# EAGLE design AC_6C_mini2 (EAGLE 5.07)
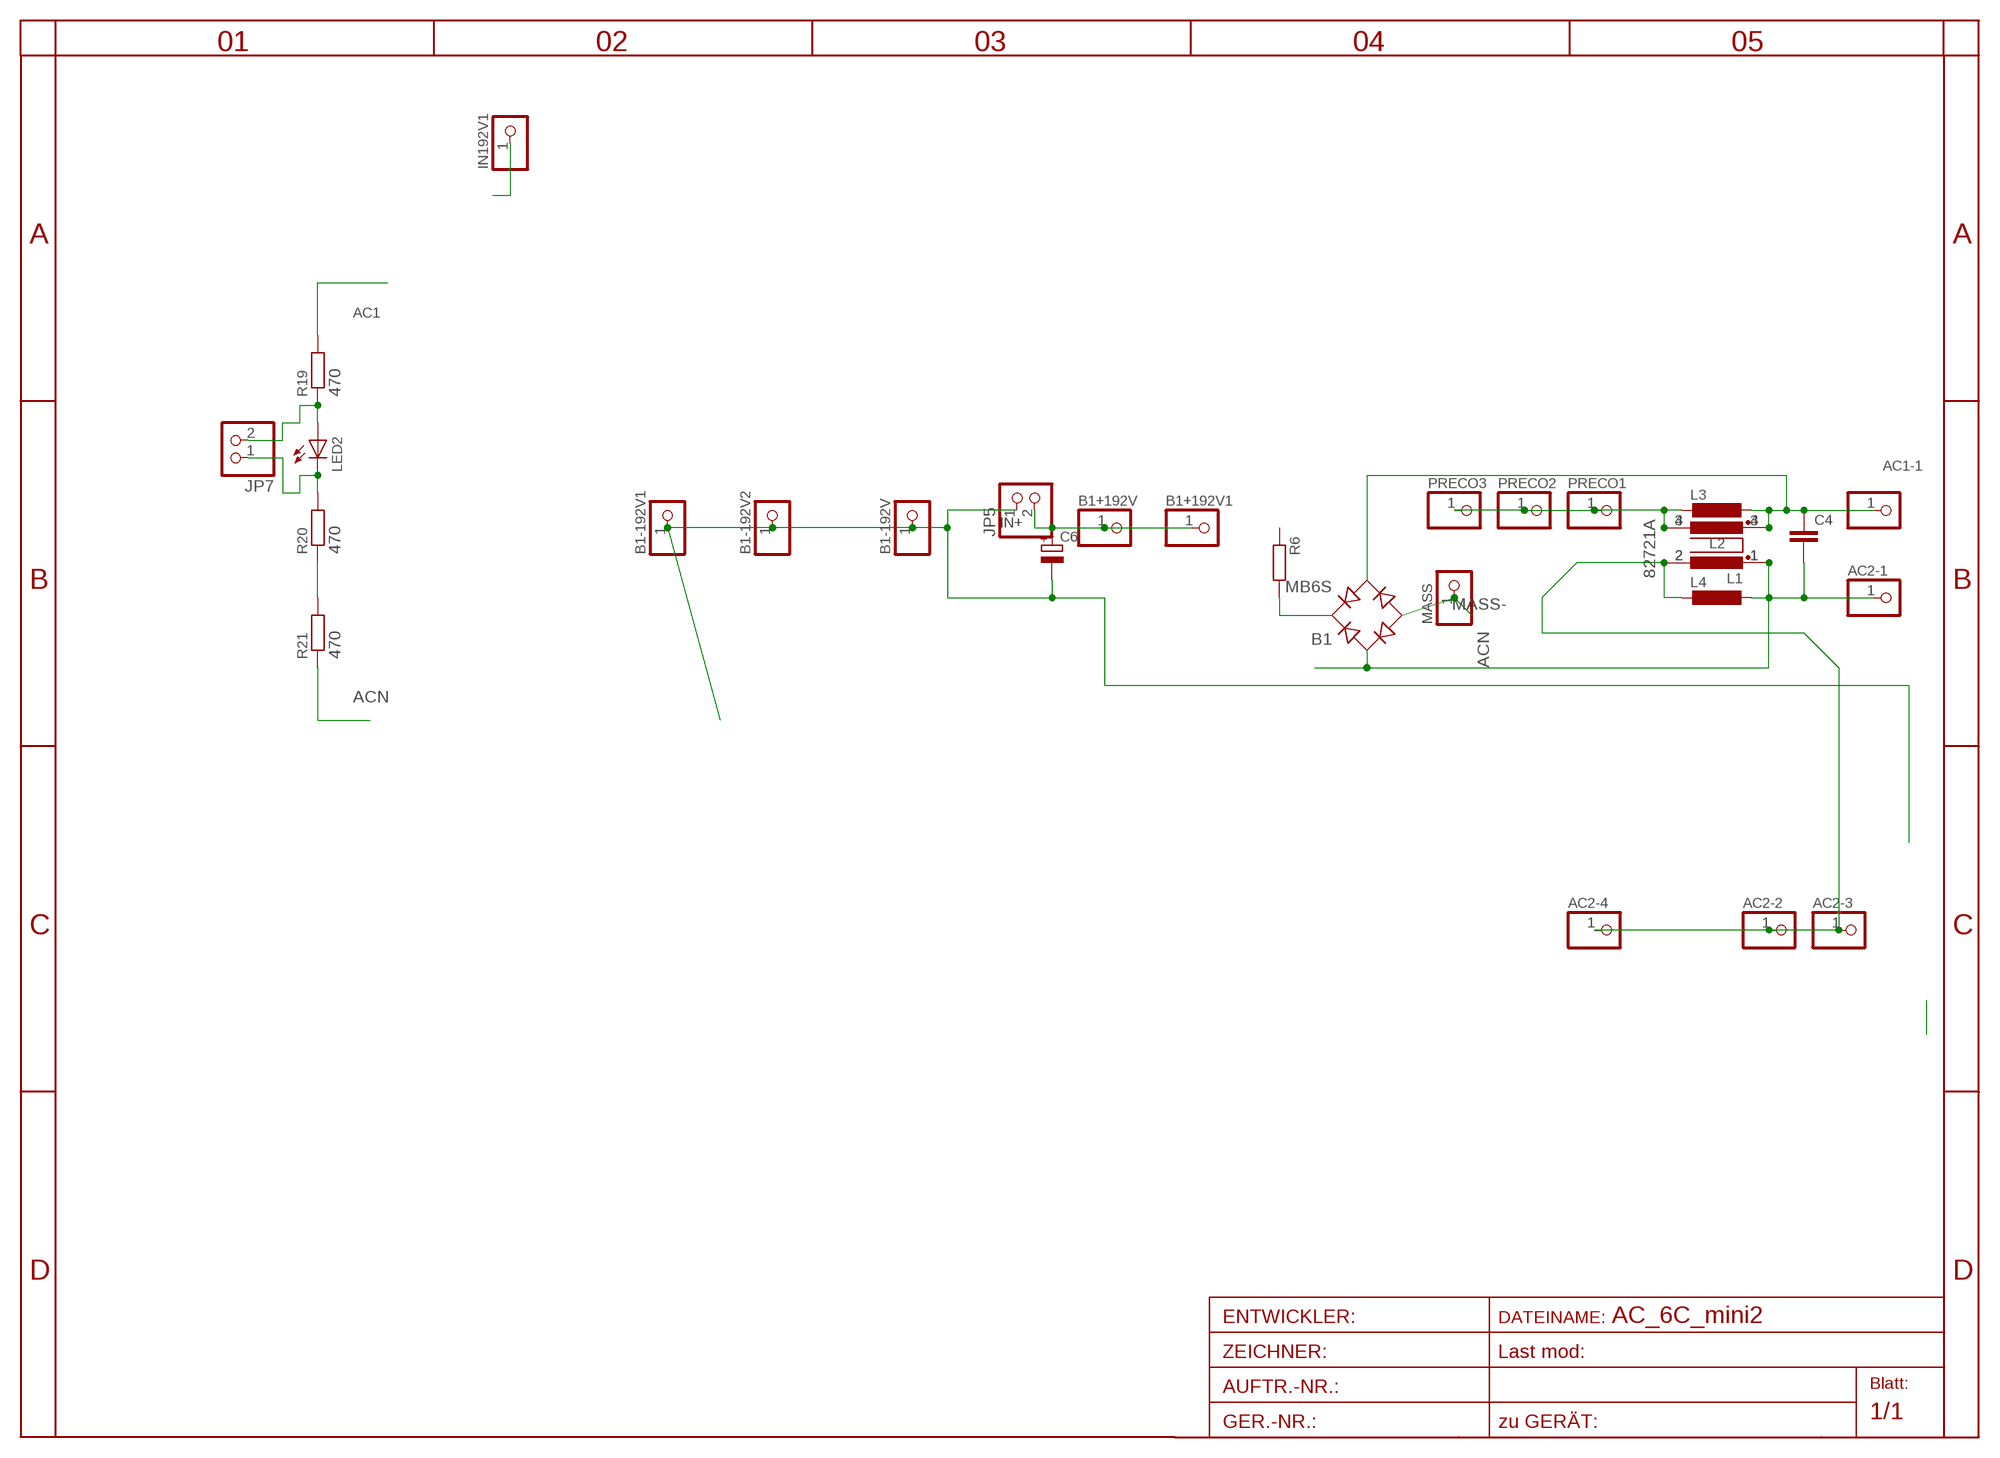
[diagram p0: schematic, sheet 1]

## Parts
AC1-1  PINHD-1X14.5MM  [1X4MM5]
AC2-1  PINHD-1X14.5MM  [1X4MM5]
AC2-2  PINHD-1X13MM2  [1X3MM2]
AC2-3  PINHD-1X13MM2  [1X3MM2]
AC2-4  PINHD-1X12MM3  [1X2MM3]
B1  MB6S  [SOIC-4]
B1+192V  PINHD-1X13MM2  [1X3MM2]
B1+192V1  PINHD-1X13MM2  [1X3MM2]
B1-192V  PINHD-1X13MM2  [1X3MM2]
B1-192V1  PINHD-1X13MM2  [1X3MM2]
B1-192V2  PINHD-1X13MM2  [1X3MM2]
C4  C-EU102-043X133  [C102-043X133]
C6  CPOL-EUE10-20  [EB20D]
IN192V1  PINHD-1X13MM2  [1X3MM2]
JP5  PINHD-1X2STR  [1X02]
JP7  PINHD-1X2STR  [1X02]
L1  R1405VB1  [B1]
L2  82721A  [82721A]
L3  L-EU2200-15.24  [2200-15.24]
L4  L-EU2200-15.24  [2200-15.24]
LED2  LED3MM  [LED3MM]
MASS  PINHD-1X13MM2  [1X3MM2]
PRECO1  PINHD-1X12MM3  [1X2MM3]
PRECO2  PINHD-1X13MM2  [1X3MM2]
PRECO3  PINHD-1X13MM2  [1X3MM2]
R6  R-EU_0207/60  [0207/60]
R19  470  R-EU_0204/5  [0204/5]
R20  470  R-EU_0204/2V  [0204V]
R21  470  R-EU_0204/5  [0204/5]

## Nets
AC1: AC1-1.1 B1.~2(AC2) C4.1 L1.3 L2.4 L3.1 R19.2
ACN: AC2-1.1 B1.~1(AC1) C4.2 L1.1 L2.1 L4.1 R21.1
IN+: B1+192V1.1 B1+192V.1 C6.+ IN192V1.1 JP5.2
INN: AC2-2.1 AC2-3.1 AC2-4.1 L1.2 L2.2 L4.2
MASS-: B1-192V1.1 B1-192V2.1 B1-192V.1 B1.- C6.- JP5.1 MASS.1
N$6: JP7.2 LED2.A R19.1
N$9: JP7.1 LED2.K(C) R20.2
N$13: R20.1 R21.2
N$33: B1.+ R6.2
PRECOIL: L1.4 L2.3 L3.2 PRECO1.1 PRECO2.1 PRECO3.1
Unconnected: R6.1

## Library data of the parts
AC1-1 AC2-1-AC2-4 B1+192V B1+192V1 B1-192V B1-192V1 B1-192V2 IN192V1 MASS PRECO1-PRECO3 = pinhead:PINHD-1X1: PIN HEADER
B1 = rectifier:MB*S: Bridge Rectifier Source: http://www.fairchildsemi.com/ds/MB/MB6S.pdf
C4 = rcl:C-EU: CAPACITOR, European symbol
C6 = rcl:CPOL-EU: POLARIZED CAPACITOR, European symbol
JP5 JP7 = pinhead:PINHD-1X2: PIN HEADER
L1 = inductor-nkl:R1405V: Übertrager (verlustarm) bis typ. 400kHz Power transformer (low loss) up to typ. 400kHz
L2 = inductors:82721A: FILTER
L3 L4 = rcl:L-EU: INDUCTOR, European symbol
LED2 = led:LED: LED
R6 R19-R21 = rcl-2:R-EU_: RESISTOR, European symbol

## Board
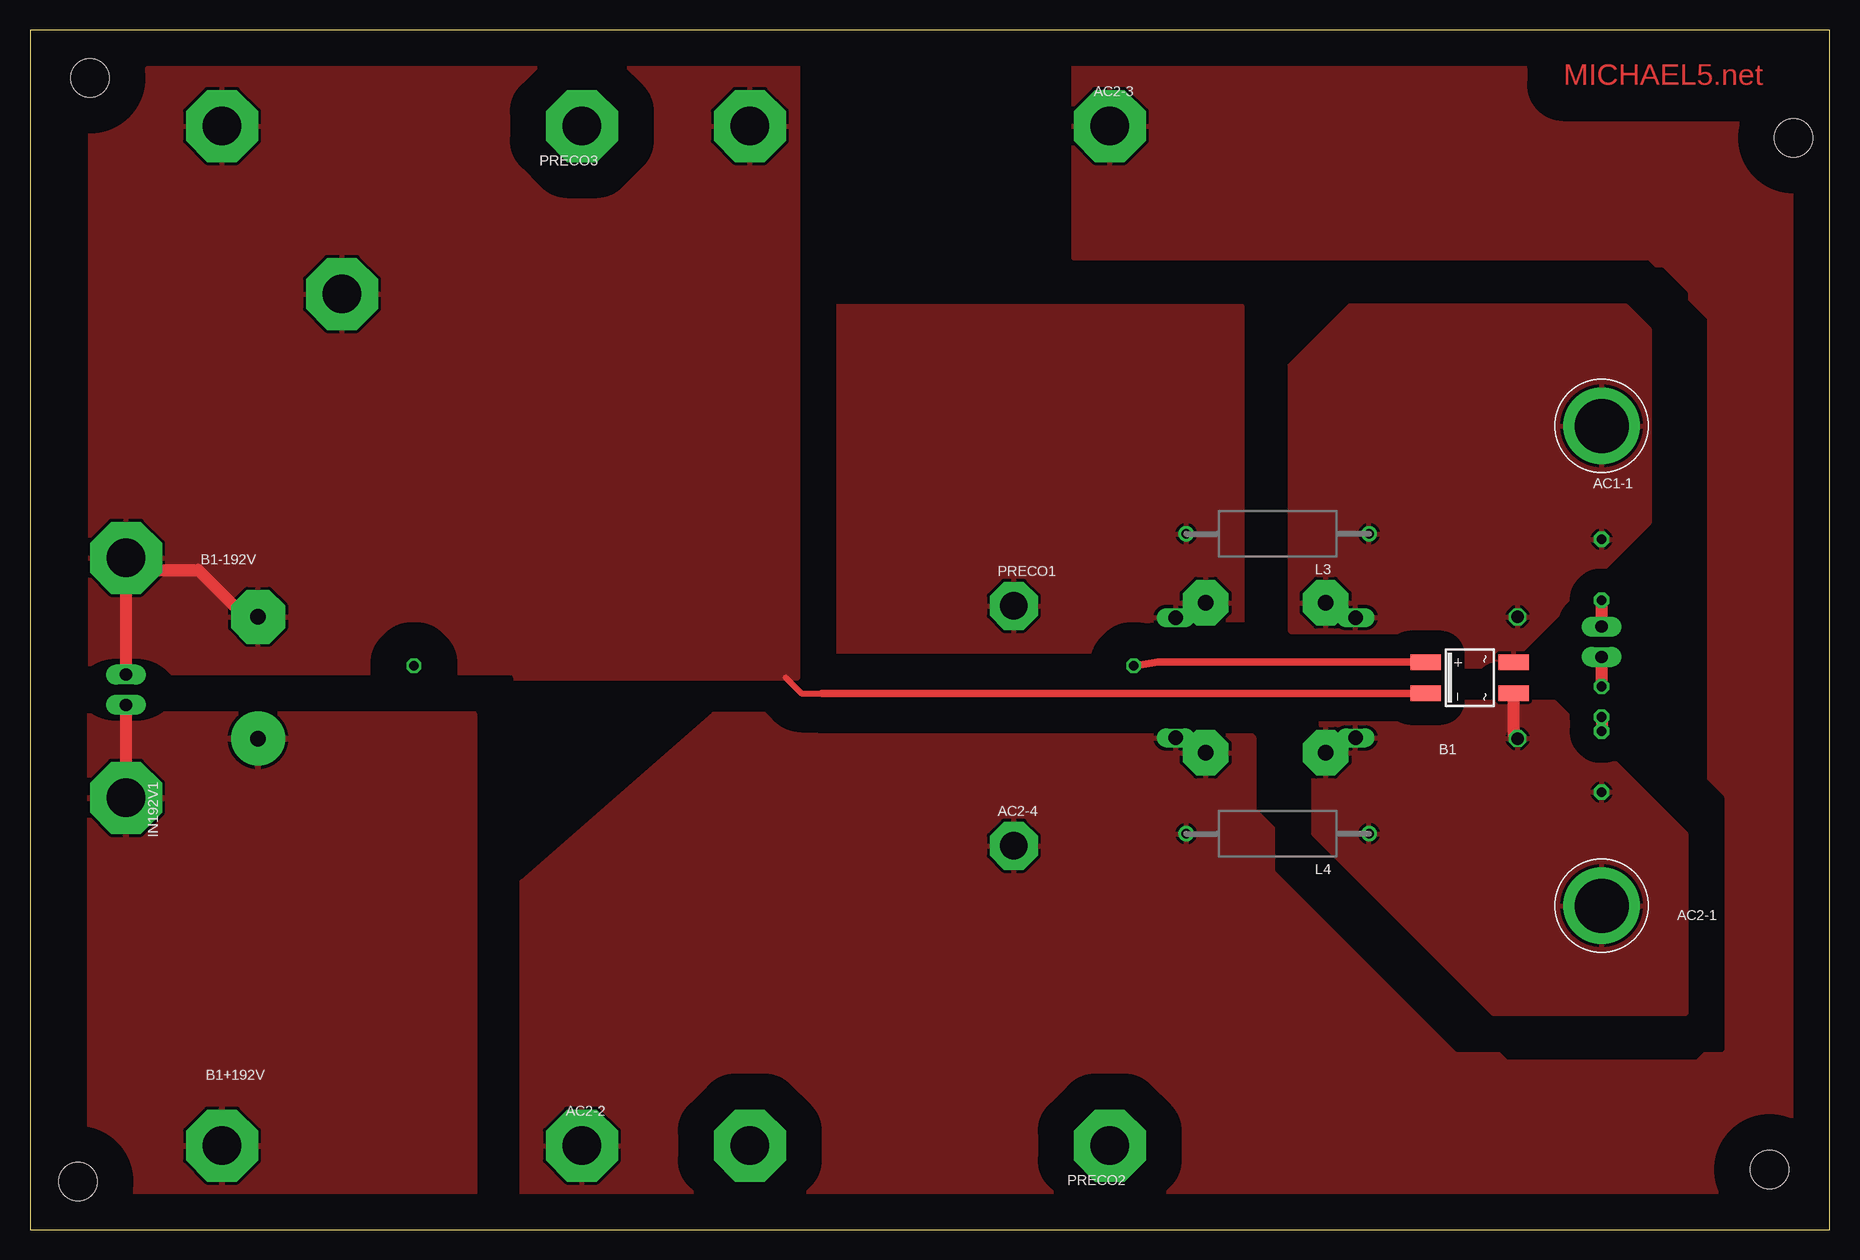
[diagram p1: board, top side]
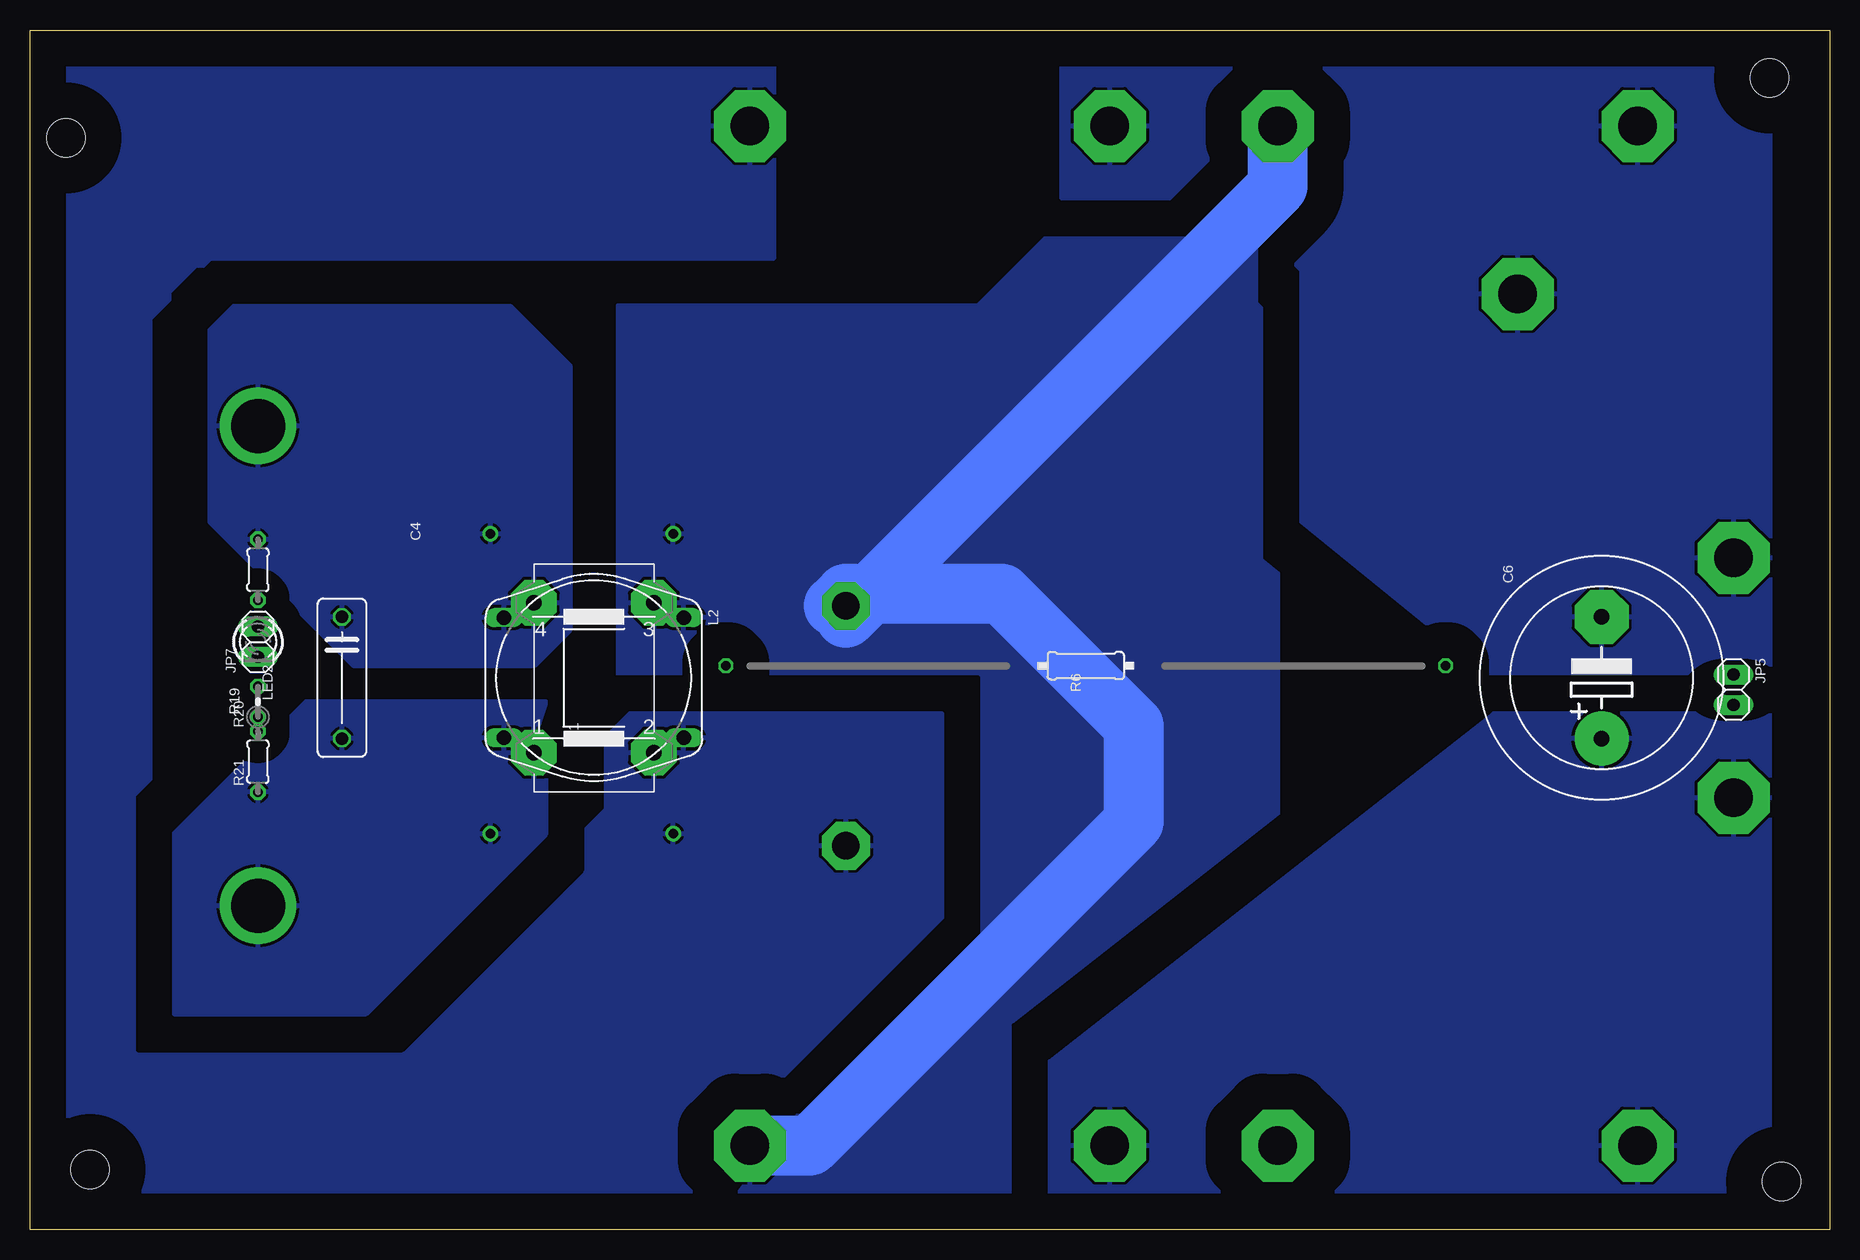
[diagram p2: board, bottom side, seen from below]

Size 150 x 100 mm. Coordinates in mm from the lower left corner, seen from the top.
Outline: 0,0 150,0 150,100 0,100 0,0
Copper layers (1*16): Top 0.035mm / dielectric 1.5mm / Bottom 0.035mm
Design rules "default *": minimum track width 12mil, minimum drill 24mil, track to track 8mil, track to pad 8mil, pad to pad 8mil, via to via 8mil, smd to smd 8mil, copper to edge 40mil, drill to drill 8mil, minimum pad ring 8mil, minimum via ring 8mil, stop-mask expansion 4mil, vias tented up to drill 0mil, thermal gap 10mil
Holes 3.2 mm at 5,96 4,4 147,91 145,5

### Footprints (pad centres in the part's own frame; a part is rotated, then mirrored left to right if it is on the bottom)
1X4MM5 = drill 4.5 pad 6.35 round: 1 0,0
1X3MM2 = drill 3.2 pad 6 octagon: 1 0,0
1X2MM3 = drill 2.3 pad 4 octagon: 1 0,0
SOIC-4 = smd 1.27 x 2.54: + 1.3,3.685; - -1.3,3.685; ~1 -1.3,-3.685; ~2 1.3,-3.685
C102-043X133 = drill 1.016 octagon: 1 -5.08,0; 2 5.08,0
EB20D = drill 1.3 pad 4.5 round: + -5.08,0 | drill 1.3 pad 4.5 octagon: - 5.08,0
1X02 = drill 1.016 pad 1.676 long: 1 -1.27,0; 2 1.27,0
B1 = drill 1.27 pad 3.81 octagon: 1 -6.25,5; 2 -6.25,-5; 3 6.25,5; 4 6.25,-5
82721A = drill 1.194 long: 1 7.493,5.004; 2 -7.493,5.004; 3 -7.493,-5.004; 4 7.493,-5.004
2200-15.24 = drill 0.8 pad 1.27 round: 1 -7.62,0; 2 7.62,0
LED3MM = drill 0.8 pad 1.27 octagon: A -1.27,0; K 1.27,0
0207/60 = drill 0.813 octagon: 1 -30,0; 2 30,0
0204/5 = drill 0.8 pad 1.27 octagon: 1 -2.54,0; 2 2.54,0
0204V = drill 0.8 pad 1.27 octagon: 1 -1.27,0; 2 1.27,0

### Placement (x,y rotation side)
AC1-1  131,67 180 top
AC2-1  131,27 180 top
AC2-2  46,7 0 top
AC2-3  90,92 0 top
AC2-4  82,32 0 top
B1  120,46 90 top
B1+192V  16,7 0 top
B1+192V1  60,7 0 top
B1-192V  8,56 180 top
B1-192V1  16,92 180 top
B1-192V2  60,92 0 top
C4  124,46 270 bottom
C6  19,46 90 bottom
IN192V1  8,36 270 top
JP5  8,45 270 bottom
JP7  131,49 90 bottom
L1  103,46 90 bottom
L2  103,46 180 bottom
L3  104,58 180 top
L4  104,33 180 top
LED2  131,49 270 bottom
MASS  26,78 0 top
PRECO1  82,52 0 top
PRECO2  90,7 180 top
PRECO3  46,92 180 top
R6  62,47 180 bottom
R19  131,55 90 bottom
R20  131,44 90 bottom
R21  131,39 90 bottom

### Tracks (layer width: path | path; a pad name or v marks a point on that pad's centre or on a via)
AC1
  pour Bottom (isolate 2): 105,72 105,50 108,47 123,47 135,59 135,75 133,77 110,77
  pour Top (isolate 2): 105,72 105,50 108,47 123,47 135,59 135,75 133,77 110,77
ACN
  Top 1: B1.~1 123.69,41.23 C4.2
  pour Bottom (isolate 2, rank 2): 107,44 127,44 138,33 138,18 122,18 107,33 107,40 108,41
  pour Top (isolate 2, rank 2): 107,44 127,44 138,33 138,18 122,18 107,33 107,40 108,41
IN+
  Top 1: IN192V1.1 JP5.2
  pour Bottom (isolate 3): 5,2 5,43 28,43 65,14 65,2
  pour Top (isolate 3): 5,43 37,43 37,3 5,3
INN
  pour Top (isolate 3, rank 3): 87,98 148,98 147,3 41,3 41,29 57,43 100,43 102,41 102,35 123,14 139,14 140,15 140,76 135,81 87,81
  pour Bottom (isolate 3, rank 3): 88,97 148,97 148,2 93,2 74,22 74,43 100,43 102,41 102,35 122,15 140,15 140,76 135,81 88,81
MASS-
  Top 0.5: 66,44.7 64.3,44.7 63,46
  Top 0.61: 66,44.7 B1.-
  Top 1: JP5.1 8,55 | 8,55 9,56 | 8,55 14,55 19,50 C6.-
  pour Bottom (isolate 3, rank 2): 5,46 28,46 44,59 44,80 50,86 64,86 64,97 10,97 5,92
  pour Top (isolate 3, rank 3): 5,46 64,46 64,97 10,97 5,92
N$6
  Top 1: JP7.2 R19.1
N$9
  Top 1: R20.2 JP7.1
N$13
  Top 1: R20.1 R21.2
N$33
  Top 0.61: B1.+ 94,47.3 R6.2
PRECOIL
  Bottom 5: PRECO3.1 46,87 82,51 | PRECO2.1 85,7 58,34 58,42 69,53 82,53 83,52
  pour Bottom (isolate 3, rank 5): 46,25 46,81 50,85 63,85 71,77 101,77 101,46 72,28 91,3 68,3 61,15
  pour Top (isolate 3, rank 5): 67,46 67,77 101,77 101,46

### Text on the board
Top: MICHAEL5.net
